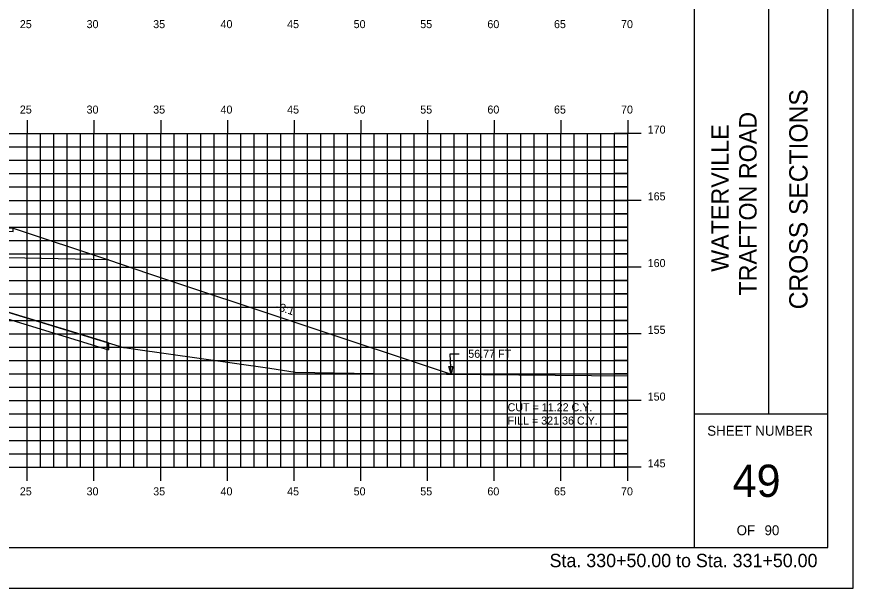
# Model space of a CAD drawing. Extents: x 1141424 to 1141594, y 608981 to 609091.
# Drawn here: x 1141531.5 to 1141594.2, y 608981.3 to 609024.1 of the extents above; entities that cross this region are included whole.
import ezdxf

# ---------------------------------------------------------------- set-up
doc = ezdxf.new("R2010")
doc.units = 0
for name, color, linetype in [('ANNOTATION', 7, 'Continuous'), ('BORDER', 7, 'Continuous'), ('D_Roadway_SlopeLines', 7, 'Continuous'), ('D_Roadway_SubGrade', 7, 'Continuous'), ('D_Text_Standard', 7, 'Continuous'), ('H_V ANNOTATION', 7, 'Continuous'), ('HIGHWAY_TITLE', 7, 'Continuous'), ('MAJOR', 7, 'Continuous'), ('MINOR', 7, 'Continuous'), ('PLOT BOUNDARY', 7, 'Continuous'), ('S_Roadway_Centerline', 7, 'Continuous'), ('SHADING', 7, 'Continuous')]:
    doc.layers.add(name, color=color, linetype=linetype)

msp = doc.modelspace()

# ---------------------------------------------------------------- linework, layer by layer
msp.add_lwpolyline([(1141475.032, 609006.83), (1141478.738, 609004.977), (1141481.738, 609005.977), (1141489.27, 609008.488), (1141489.271, 609008.488), (1141496.271, 609008.768), (1141507.271, 609008.988), (1141518.271, 609008.768), (1141531.215, 609008.25), (1141538.367, 609005.866), (1141541.367, 609004.866), (1141564.044, 608997.307)])
at = {"layer": 'BORDER'}
for p, q in [((1141582.271, 608984.335), (1141582.271, 609089.335)), ((1141587.862, 608994.338), (1141587.862, 609029.338)), ((1141582.271, 608994.338), (1141592.271, 608994.338))]:
    msp.add_line(p, q, dxfattribs=at)
msp.add_lwpolyline([(1141432.271, 608984.335), (1141592.271, 608984.335), (1141592.271, 609089.335), (1141432.271, 609089.335)], close=True, dxfattribs=at)
at = {"layer": 'D_Roadway_SlopeLines'}
msp.add_line((1141538.367, 608999.661), (1141538.367, 608999.138), dxfattribs=at)
for points in [[(1141538.367, 609005.866), (1141541.367, 609004.866)], [(1141520.14, 609004.691), (1141520.296, 609004.684), (1141522.725, 609004.261), (1141522.76, 609004.239), (1141526.82, 609002.422), (1141527.221, 609002.26), (1141528.809, 609002.048), (1141538.367, 608999.138)], [(1141541.367, 609004.866), (1141564.044, 608997.307)]]:
    msp.add_lwpolyline(points, dxfattribs=at)
at = {"layer": 'D_Roadway_SubGrade'}
msp.add_lwpolyline([(1141518.271, 609008.351), (1141518.271, 609008.518), (1141531.215, 609008), (1141531.215, 609008.25), (1141531.215, 609008.25), (1141538.367, 609005.866), (1141518.271, 609006.268)], close=True, dxfattribs=at)
at = {"layer": 'D_Text_Standard'}
msp.add_lwpolyline([(1141564.044, 608997.307), (1141563.965, 608998.841), (1141564.644, 608998.841)], dxfattribs=at)
msp.add_lwpolyline([(1141564.044, 608997.307), (1141563.869, 608997.88), (1141564.159, 608997.896)], close=True, dxfattribs=at)
at = {"layer": 'MAJOR'}
for p, q in [((1141532.271, 609016.337), (1141532.271, 609015.335)), ((1141537.271, 609016.337), (1141537.271, 609015.335)), ((1141542.271, 609016.337), (1141542.271, 609015.335)), ((1141547.271, 609016.337), (1141547.271, 609015.335)), ((1141552.271, 609016.337), (1141552.271, 609015.335)), ((1141557.271, 609016.337), (1141557.271, 609015.335)), ((1141562.271, 609016.337), (1141562.271, 609015.335)), ((1141567.271, 609016.337), (1141567.271, 609015.335)), ((1141572.271, 609016.337), (1141572.271, 609015.335)), ((1141577.271, 609016.337), (1141577.271, 609015.335)), ((1141437.271, 609015.335), (1141577.271, 609015.335)), ((1141437.271, 609015.335), (1141577.271, 609015.335)), ((1141532.271, 608990.335), (1141532.271, 609015.335)), ((1141537.271, 608990.335), (1141537.271, 609015.335)), ((1141542.271, 608990.335), (1141542.271, 609015.335)), ((1141547.271, 608990.335), (1141547.271, 609015.335)), ((1141552.271, 608990.335), (1141552.271, 609015.335)), ((1141557.271, 608990.335), (1141557.271, 609015.335)), ((1141562.271, 608990.335), (1141562.271, 609015.335)), ((1141567.271, 608990.335), (1141567.271, 609015.335)), ((1141572.271, 608990.335), (1141572.271, 609015.335)), ((1141578.273, 609015.335), (1141576.269, 609015.335)), ((1141577.271, 608990.335), (1141577.271, 609015.335)), ((1141577.271, 608990.335), (1141577.271, 609015.335)), ((1141437.271, 609010.335), (1141577.271, 609010.335)), ((1141578.273, 609010.335), (1141576.269, 609010.335)), ((1141437.271, 609005.335), (1141577.271, 609005.335)), ((1141578.273, 609005.335), (1141576.269, 609005.335)), ((1141437.271, 609000.335), (1141577.271, 609000.335)), ((1141578.273, 609000.335), (1141576.269, 609000.335)), ((1141437.271, 608995.335), (1141577.271, 608995.335)), ((1141578.273, 608995.335), (1141576.269, 608995.335)), ((1141437.271, 608990.335), (1141577.271, 608990.335)), ((1141437.271, 608990.335), (1141577.271, 608990.335)), ((1141532.271, 608989.333), (1141532.271, 608990.335)), ((1141537.271, 608989.333), (1141537.271, 608990.335)), ((1141542.271, 608989.333), (1141542.271, 608990.335)), ((1141547.271, 608989.333), (1141547.271, 608990.335)), ((1141552.271, 608989.333), (1141552.271, 608990.335)), ((1141557.271, 608989.333), (1141557.271, 608990.335)), ((1141562.271, 608989.333), (1141562.271, 608990.335)), ((1141567.271, 608989.333), (1141567.271, 608990.335)), ((1141572.271, 608989.333), (1141572.271, 608990.335)), ((1141578.273, 608990.335), (1141576.269, 608990.335)), ((1141577.271, 608989.333), (1141577.271, 608990.335))]:
    msp.add_line(p, q, dxfattribs=at)
at = {"layer": 'MINOR'}
for p, q in [((1141533.271, 608990.335), (1141533.271, 609015.335)), ((1141534.271, 608990.335), (1141534.271, 609015.335)), ((1141535.271, 608990.335), (1141535.271, 609015.335)), ((1141536.271, 608990.335), (1141536.271, 609015.335)), ((1141538.271, 608990.335), (1141538.271, 609015.335)), ((1141539.271, 608990.335), (1141539.271, 609015.335)), ((1141540.271, 608990.335), (1141540.271, 609015.335)), ((1141541.271, 608990.335), (1141541.271, 609015.335)), ((1141543.271, 608990.335), (1141543.271, 609015.335)), ((1141544.271, 608990.335), (1141544.271, 609015.335)), ((1141545.271, 608990.335), (1141545.271, 609015.335)), ((1141546.271, 608990.335), (1141546.271, 609015.335)), ((1141548.271, 608990.335), (1141548.271, 609015.335)), ((1141549.271, 608990.335), (1141549.271, 609015.335)), ((1141550.271, 608990.335), (1141550.271, 609015.335)), ((1141551.271, 608990.335), (1141551.271, 609015.335)), ((1141553.271, 608990.335), (1141553.271, 609015.335)), ((1141554.271, 608990.335), (1141554.271, 609015.335)), ((1141555.271, 608990.335), (1141555.271, 609015.335)), ((1141556.271, 608990.335), (1141556.271, 609015.335)), ((1141558.271, 608990.335), (1141558.271, 609015.335)), ((1141559.271, 608990.335), (1141559.271, 609015.335)), ((1141560.271, 608990.335), (1141560.271, 609015.335)), ((1141561.271, 608990.335), (1141561.271, 609015.335)), ((1141563.271, 608990.335), (1141563.271, 609015.335)), ((1141564.271, 608990.335), (1141564.271, 609015.335)), ((1141565.271, 608990.335), (1141565.271, 609015.335)), ((1141566.271, 608990.335), (1141566.271, 609015.335)), ((1141568.271, 608990.335), (1141568.271, 609015.335)), ((1141569.271, 608990.335), (1141569.271, 609015.335)), ((1141570.271, 608990.335), (1141570.271, 609015.335)), ((1141571.271, 608990.335), (1141571.271, 609015.335)), ((1141573.271, 608990.335), (1141573.271, 609015.335)), ((1141574.271, 608990.335), (1141574.271, 609015.335)), ((1141575.271, 608990.335), (1141575.271, 609015.335)), ((1141576.271, 608990.335), (1141576.271, 609015.335)), ((1141437.271, 609014.335), (1141577.271, 609014.335)), ((1141577.271, 609014.335), (1141576.269, 609014.335)), ((1141437.271, 609013.335), (1141577.271, 609013.335)), ((1141577.271, 609013.335), (1141576.269, 609013.335)), ((1141437.271, 609012.335), (1141577.271, 609012.335)), ((1141577.271, 609012.335), (1141576.269, 609012.335)), ((1141437.271, 609011.335), (1141577.271, 609011.335)), ((1141577.271, 609011.335), (1141576.269, 609011.335)), ((1141437.271, 609009.335), (1141577.271, 609009.335)), ((1141577.271, 609009.335), (1141576.269, 609009.335)), ((1141437.271, 609008.335), (1141577.271, 609008.335)), ((1141577.271, 609008.335), (1141576.269, 609008.335)), ((1141437.271, 609007.335), (1141577.271, 609007.335)), ((1141577.271, 609007.335), (1141576.269, 609007.335)), ((1141437.271, 609006.335), (1141577.271, 609006.335)), ((1141577.271, 609006.335), (1141576.269, 609006.335)), ((1141437.271, 609004.335), (1141577.271, 609004.335)), ((1141577.271, 609004.335), (1141576.269, 609004.335)), ((1141437.271, 609003.335), (1141577.271, 609003.335)), ((1141577.271, 609003.335), (1141576.269, 609003.335)), ((1141437.271, 609002.335), (1141577.271, 609002.335)), ((1141577.271, 609002.335), (1141576.269, 609002.335)), ((1141437.271, 609001.335), (1141577.271, 609001.335)), ((1141577.271, 609001.335), (1141576.269, 609001.335)), ((1141437.271, 608999.335), (1141577.271, 608999.335)), ((1141577.271, 608999.335), (1141576.269, 608999.335)), ((1141437.271, 608998.335), (1141577.271, 608998.335)), ((1141577.271, 608998.335), (1141576.269, 608998.335)), ((1141437.271, 608997.335), (1141577.271, 608997.335)), ((1141577.271, 608997.335), (1141576.269, 608997.335)), ((1141437.271, 608996.335), (1141577.271, 608996.335)), ((1141577.271, 608996.335), (1141576.269, 608996.335)), ((1141437.271, 608994.335), (1141577.271, 608994.335)), ((1141577.271, 608994.335), (1141576.269, 608994.335)), ((1141437.271, 608993.335), (1141577.271, 608993.335)), ((1141577.271, 608993.335), (1141576.269, 608993.335)), ((1141437.271, 608992.335), (1141577.271, 608992.335)), ((1141577.271, 608992.335), (1141576.269, 608992.335)), ((1141437.271, 608991.335), (1141577.271, 608991.335)), ((1141577.271, 608991.335), (1141576.269, 608991.335))]:
    msp.add_line(p, q, dxfattribs=at)
at = {"layer": 'PLOT BOUNDARY'}
msp.add_lwpolyline([(1141424.178, 608981.276), (1141594.178, 608981.276), (1141594.178, 609091.276), (1141424.178, 609091.276)], close=True, dxfattribs=at)
at = {"layer": 'S_Roadway_Centerline'}
msp.add_lwpolyline([(1141528.916, 609002.539), (1141539.494, 608999.318), (1141539.557, 608999.306), (1141540.211, 608999.204), (1141550.447, 608997.763), (1141552.348, 608997.454), (1141558.24, 608997.354), (1141577.271, 608997.2)], dxfattribs=at)
at = {"layer": 'SHADING'}
msp.add_lwpolyline([(1141520.14, 609005.191), (1141520.14, 609004.691), (1141522.725, 609004.261), (1141527.221, 609002.26), (1141528.809, 609002.048), (1141538.367, 608999.138), (1141538.367, 608999.661), (1141528.916, 609002.539), (1141527.349, 609002.748), (1141525.006, 609003.782), (1141522.997, 609004.681), (1141522.908, 609004.737), (1141520.35, 609005.182)], close=True, dxfattribs=at)

# ---------------------------------------------------------------- texts
at = {"layer": 'ANNOTATION'}
msp.add_text('-3:1', height=0.6, rotation=341.56505, dxfattribs=at).set_placement((1141550.855, 609002.157))
at = {"layer": 'BORDER'}
msp.add_text('CROSS SECTIONS', height=1.37787, rotation=90, dxfattribs=at).set_placement((1141590.755, 609002.172))
for s, height, p in [('SHEET NUMBER', 0.74527, (1141583.236, 608992.701)), ('49', 2.4194, (1141585.132, 608988.118)), ('OF', 0.7453, (1141585.438, 608985.248)), ('90', 0.7453, (1141587.527, 608985.248))]:
    msp.add_text(s, height=height, dxfattribs=at).set_placement(p)
at = {"layer": 'D_Text_Standard'}
for s, p in [('56.77 FT', (1141565.324, 608998.541)), ('CUT = 11.22 C.Y.', (1141568.271, 608994.535)), ('FILL = 321.36 C.Y.', (1141568.271, 608993.539))]:
    msp.add_text(s, height=0.6, dxfattribs=at).set_placement(p)
at = {"layer": 'H_V ANNOTATION'}
for s, height, p in [('25', 0.6, (1141531.717, 609023.235)), ('30', 0.6, (1141536.719, 609023.235)), ('35', 0.6, (1141541.711, 609023.235)), ('40', 0.6, (1141546.757, 609023.235)), ('45', 0.6, (1141551.749, 609023.235)), ('50', 0.6, (1141556.735, 609023.235)), ('55', 0.6, (1141561.727, 609023.235)), ('60', 0.6, (1141566.757, 609023.235)), ('65', 0.6, (1141571.749, 609023.235)), ('70', 0.6, (1141576.773, 609023.235)), ('25', 0.6, (1141531.717, 609016.835)), ('30', 0.6, (1141536.719, 609016.835)), ('35', 0.6, (1141541.711, 609016.835)), ('40', 0.6, (1141546.757, 609016.835)), ('45', 0.6, (1141551.749, 609016.835)), ('50', 0.6, (1141556.735, 609016.835)), ('55', 0.6, (1141561.727, 609016.835)), ('60', 0.6, (1141566.757, 609016.835)), ('65', 0.6, (1141571.749, 609016.835)), ('70', 0.6, (1141576.773, 609016.835)), ('170', 0.6, (1141578.771, 609015.335)), ('165', 0.6, (1141578.771, 609010.335)), ('160', 0.6, (1141578.771, 609005.335)), ('155', 0.6, (1141578.771, 609000.335)), ('150', 0.6, (1141578.771, 608995.335)), ('145', 0.6, (1141578.771, 608990.335)), ('25', 0.6, (1141531.717, 608988.235)), ('30', 0.6, (1141536.719, 608988.235)), ('35', 0.6, (1141541.711, 608988.235)), ('40', 0.6, (1141546.757, 608988.235)), ('45', 0.6, (1141551.749, 608988.235)), ('50', 0.6, (1141556.735, 608988.235)), ('55', 0.6, (1141561.727, 608988.235)), ('60', 0.6, (1141566.757, 608988.235)), ('65', 0.6, (1141571.749, 608988.235)), ('70', 0.6, (1141576.773, 608988.235)), ('Sta. 330+50.00 to Sta. 331+50.00', 1.0002, (1141571.417, 608982.855))]:
    msp.add_text(s, height=height, dxfattribs=at).set_placement(p)
at = {"layer": 'HIGHWAY_TITLE'}
for s, height, p in [('TRAFTON ROAD', 1.30428, (1141586.93, 609003.201)), ('WATERVILLE', 1.3043, (1141584.843, 609004.98))]:
    msp.add_text(s, height=height, rotation=90, dxfattribs=at).set_placement(p)

doc.saveas('drawing.dxf')
